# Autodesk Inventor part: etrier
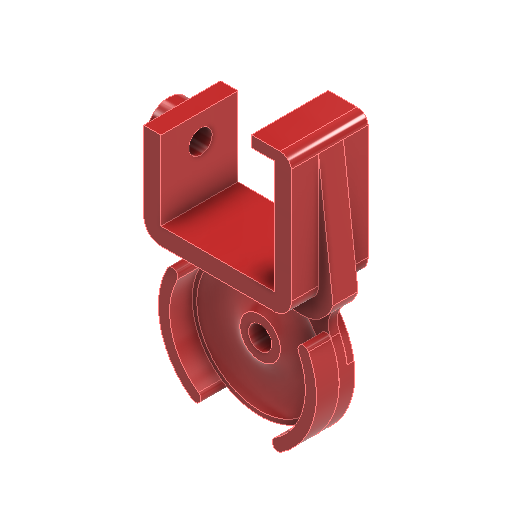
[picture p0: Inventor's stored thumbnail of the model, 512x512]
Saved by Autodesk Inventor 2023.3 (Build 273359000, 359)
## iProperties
Created: 2024-11
Part Number: etrier
Material: Générique
Description: STEP AP203
Document SubType Name: Modeling
Designer: Thier
Density: 1 g/cm^3
Appearance: Rouge
Sending System: SolidWorks 2017
Preprocessor: SwSTEP 2.0
Title: etrier.STEP
Revision Number: ANY
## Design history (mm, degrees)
feature "Enlèv. mat.-Extru.23"
node "Solide1"
